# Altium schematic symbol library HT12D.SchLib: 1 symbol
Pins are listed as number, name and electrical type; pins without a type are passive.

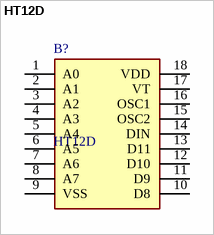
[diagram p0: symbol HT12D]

## HT12D
designator B?
212 Series of Decoders; Manufacturer_Name: Holtek; Geometry.Height: 4.953mm
footprint DIP794W56P254L2286H495Q18N
pins: 1 A0, 2 A1, 3 A2, 4 A3, 5 A4, 6 A5, 7 A6, 8 A7, 9 VSS, 10 D8, 11 D9, 12 D10, 13 D11, 14 DIN, 15 OSC2, 16 OSC1, 17 VT, 18 VDD (power)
